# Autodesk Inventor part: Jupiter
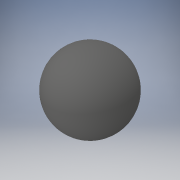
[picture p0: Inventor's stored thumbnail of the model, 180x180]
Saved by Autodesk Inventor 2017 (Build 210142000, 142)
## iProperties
Created: 2016-07
Part Number: Jupiter
Material: Generic
Document SubType Name: Modeling
Designer: Stan
Density: 1 g/cm^3
Appearance: Gray
Author: Stan
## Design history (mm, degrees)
sketch "Sketch1"
  geometry: L1 (0, 26.988)-(0, -20.45); L2 (-3.175, -26.8)-(-1.587, -26.8); L3 (-1.587, -26.8)-(-1.587, -20.45); L4 (-1.587, -20.45)-(0, -20.45); A1 r 26.988 centre (0, 0) between (0, 26.988) and (-3.175, -26.8); 1 further point
  constraints: 8 end point, 2 point on circle, 2 vertical, 1 centre point, 1 horizontal, 1 perpendicular
  dimensions: "d0" = 53.975 diameter of A1; "d7" = 0 distance of point (0, 0) A1.centre; "d20" = 1.5875 distance of L1.end L3.end; "d21" = 0 distance from line of point (0, 0) L1; "d23" = 3.175 horizontal distance of L2.start L1.end; "d24" = 6.35 distance of L2.end L3.end
revolve "Revolution2" sketch "Sketch1" stored, may be unused: angle "d25" = 90 deg
body "Solid2"
